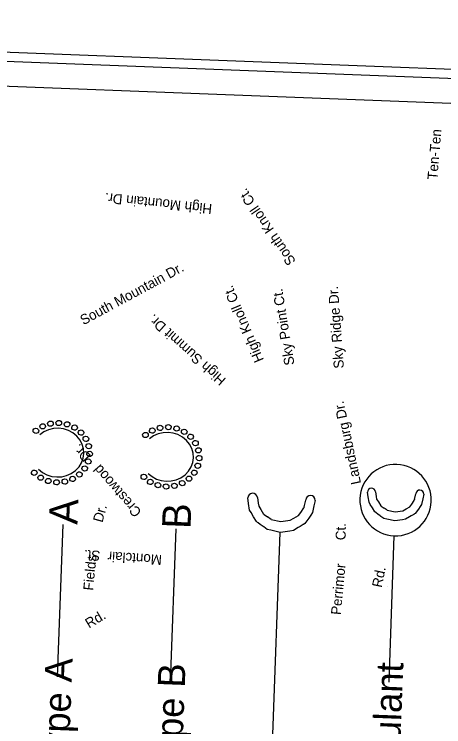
# Model space of a CAD drawing. Extents: x 1654773 to 2116434, y 680831 to 888488.
# Drawn here: x 2112569 to 2113644, y 699067 to 700848 of the extents above; entities that cross this region are included whole.
import ezdxf

# ---------------------------------------------------------------- set-up
doc = ezdxf.new("R2010")
doc.units = 0
for name, color, linetype in [('EC Title Sheet CELL', 7, 'Continuous'), ('Exist Road Non-System Type 51 Label', 7, 'Continuous'), ('Exist Road Secondary Type 51 Label', 7, 'Continuous'), ('Scratch_Level_6', 7, 'Continuous'), ('Sheet Plot Border Inside CELL', 7, 'Continuous'), ('Sheet Plot Border Outside CELL', 7, 'Continuous')]:
    doc.layers.add(name, color=color, linetype=linetype)

msp = doc.modelspace()

# ---------------------------------------------------------------- linework, layer by layer
at = {"layer": 'EC Title Sheet CELL'}
for p, q in [((2112677.5, 699192.2), (2112691.7, 699573.1)), ((2112960.3, 699178.9), (2112974.5, 699562.2)), ((2113199.7, 698582.8), (2113235, 699552.9)), ((2113507.1, 699178.4), (2113519.9, 699544.4))]:
    msp.add_line(p, q, dxfattribs=at)
for centre, major_axis in [((2112640.4, 699818), (-7.07, 0.27)), ((2112659.9, 699824.7), (-7.07, 0.27)), ((2112680.7, 699826.4), (-7.07, 0.27)), ((2112701.3, 699823.1), (-7.07, 0.27)), ((2112720.2, 699814.9), (-7.07, 0.27)), ((2112934.1, 699814.1), (-7.07, 0.27)), ((2112954.9, 699815.9), (-7.07, 0.27)), ((2112623.4, 699806.9), (-7.07, 0.27)), ((2112736.3, 699802.5), (-7.07, 0.27)), ((2112897.6, 699796.3), (-7.07, 0.27)), ((2112914.6, 699807.5), (-7.07, 0.27)), ((2112975.5, 699812.6), (-7.07, 0.27)), ((2112994.5, 699804.4), (-7.07, 0.27)), ((2112748.4, 699786.7), (7.07, -0.27)), ((2113010.5, 699792), (-7.07, 0.27)), ((2112755.7, 699768.5), (7.07, -0.27)), ((2113022.6, 699776.2), (7.07, -0.27)), ((2112757.7, 699749.2), (7.07, -0.27)), ((2113029.9, 699758), (7.07, -0.27)), ((2112754.3, 699730.2), (7.07, -0.27)), ((2113031.9, 699738.7), (7.07, -0.27)), ((2112745.6, 699712.6), (7.07, -0.27)), ((2113028.5, 699719.6), (7.07, -0.27)), ((2112619.3, 699702.1), (7.07, -0.27)), ((2112635.4, 699689.7), (7.07, -0.27)), ((2112732.3, 699697.8), (7.07, -0.27)), ((2112893.5, 699691.6), (7.07, -0.27)), ((2113019.8, 699702.1), (7.07, -0.27)), ((2112654.4, 699681.5), (7.07, -0.27)), ((2112675, 699678.2), (7.07, -0.27)), ((2112695.8, 699680), (7.07, -0.27)), ((2112715.3, 699686.6), (7.07, -0.27)), ((2112909.6, 699679.2), (7.07, -0.27)), ((2112989.5, 699676.1), (7.07, -0.27)), ((2113006.5, 699687.2), (7.07, -0.27)), ((2112928.6, 699671), (7.07, -0.27)), ((2112949.2, 699667.7), (7.07, -0.27)), ((2112970, 699669.4), (7.07, -0.27))]:
    msp.add_ellipse(centre, major_axis=major_axis, ratio=0.927398, dxfattribs=at)
for centre in [(2112677.8, 699752.3), (2112952, 699741.8)]:
    msp.add_ellipse(centre, major_axis=(-65.6, 2.5), ratio=0.927398, start_param=0.785389, end_param=5.497624, dxfattribs=at)
at = {"layer": 'Exist Road Non-System Type 51 Label'}
msp.add_line((2113502.3, 699418), (2113502.1, 699418), dxfattribs=at)
at = {"layer": 'Scratch_Level_6'}
for p, q in [((2113473.4, 699654.2), (2113475.1, 699642.4)), ((2113570.8, 699635.3), (2113574, 699649.2)), ((2113177.9, 699639.9), (2113179.8, 699625.8)), ((2113179.8, 699625.8), (2113180.9, 699618.6)), ((2113294.5, 699617.2), (2113298.4, 699633.9)), ((2113475.1, 699642.4), (2113476, 699636.4)), ((2113476, 699636.4), (2113480.3, 699629.1)), ((2113480.3, 699629.1), (2113486.1, 699619.6)), ((2113563.7, 699623.5), (2113570.2, 699632.8)), ((2113570.8, 699635.3), (2113570.2, 699632.8)), ((2113180.9, 699618.6), (2113186.1, 699609.9)), ((2113186.1, 699609.9), (2113193.1, 699598.5)), ((2113286, 699603.1), (2113293.8, 699614.2)), ((2113294.5, 699617.2), (2113293.8, 699614.2)), ((2113487.6, 699618.6), (2113486.1, 699619.6)), ((2113487.6, 699618.6), (2113494.7, 699613.8)), ((2113502.3, 699608.7), (2113494.7, 699613.8)), ((2113502.3, 699608.7), (2113522, 699604.4)), ((2113522.1, 699604.4), (2113541.5, 699606.9)), ((2113541.5, 699606.9), (2113549.5, 699611.5)), ((2113549.5, 699611.5), (2113559.2, 699617)), ((2113559.2, 699617), (2113563.7, 699623.5)), ((2113194.9, 699597.3), (2113193.1, 699598.5)), ((2113194.9, 699597.3), (2113203.3, 699591.5)), ((2113212.4, 699585.4), (2113203.3, 699591.5)), ((2113269, 699588.7), (2113280.6, 699595.3)), ((2113280.6, 699595.3), (2113286, 699603.1)), ((2113522.1, 699604.4), (2113522, 699604.4)), ((2113212.4, 699585.4), (2113236.1, 699580.2)), ((2113236.2, 699580.2), (2113236.1, 699580.2)), ((2113236.2, 699580.2), (2113259.4, 699583.3)), ((2113259.4, 699583.3), (2113269, 699588.7))]:
    msp.add_line(p, q, dxfattribs=at)
msp.add_lwpolyline([(2110171.4, 700758.7), (2109883.7, 693264.2), (2115129.9, 693062.9), (2115417.5, 700557.4)], close=True, dxfattribs=at)
for points in [[(2113593.9, 699648.4), (2113591.4, 699636.7), (2113588.5, 699623.1), (2113584.8, 699617.8), (2113580.4, 699611.4), (2113572.5, 699600.1), (2113572.3, 699599.9), (2113569.4, 699598.2), (2113568.9, 699597.9), (2113562.6, 699594.1), (2113558.2, 699591.5), (2113548.5, 699585.7), (2113540.6, 699584.5), (2113521.2, 699581.6), (2113521.2, 699581.6), (2113501.4, 699586.1), (2113493.7, 699587.9), (2113486.6, 699593), (2113485.2, 699594.1), (2113479.2, 699598.4), (2113474.6, 699601.6), (2113473.6, 699602.4), (2113471.3, 699604.1), (2113471.2, 699604.1), (2113465.3, 699614.1), (2113460.1, 699623), (2113456.9, 699628.3), (2113454.8, 699641.7), (2113453, 699653.4)], [(2113322.2, 699633), (2113319.2, 699619), (2113315.7, 699602.6), (2113311.3, 699596.3), (2113306, 699588.6), (2113296.6, 699575.1), (2113296.3, 699574.9), (2113292.8, 699572.8), (2113292.2, 699572.4), (2113284.7, 699567.9), (2113279.4, 699564.8), (2113267.8, 699557.8), (2113258.4, 699556.4), (2113235.1, 699552.9), (2113235, 699552.9), (2113211.4, 699558.4), (2113202.2, 699560.5), (2113193.7, 699566.6), (2113191.9, 699567.8), (2113184.7, 699573), (2113179.3, 699576.9), (2113178, 699577.9), (2113175.3, 699579.8), (2113175.2, 699579.9), (2113168.1, 699591.9), (2113161.8, 699602.5), (2113158.1, 699608.9), (2113155.6, 699624.9), (2113153.4, 699639)]]:
    msp.add_lwpolyline(points, dxfattribs=at)
for centre, radius, start, end in [((2113523.3, 699633.6), 89.3, 357.802, 177.802), ((2113463.3, 699653), 10.3, 6.6894, 177.802), ((2113165.7, 699638.5), 12.3, 6.6894, 177.802), ((2113310.3, 699633.5), 11.9, 357.802, 177.802), ((2113584, 699648.8), 9.97, 357.802, 177.802), ((2113523.3, 699633.6), 89.3, 177.802, 357.802)]:
    msp.add_arc(centre, radius, start, end, dxfattribs=at)
at = {"layer": 'Sheet Plot Border Inside CELL'}
msp.add_lwpolyline([(2115112.9, 692295.5), (2115432.4, 700619.3), (2110161.3, 700821.7), (2109841.8, 692497.8)], close=True, dxfattribs=at)
at = {"layer": 'Sheet Plot Border Outside CELL'}
msp.add_lwpolyline([(2115210.4, 692226.7), (2115533.2, 700638), (2110062.2, 700848), (2109739.4, 692436.7)], close=True, dxfattribs=at)

# ---------------------------------------------------------------- texts
at = {"layer": 'EC Title Sheet CELL'}
for s, height, p in [('A', 71.4, (2112727.3, 699571.7)), ('B', 71.4, (2113010.2, 699560.9)), ('Rock Pipe Inlet Sediment Trap Type A', 67.733, (2112656.2, 697698.5)), ('Rock Pipe Inlet Sediment Trap Type B', 67.733, (2112939, 697685.2)), ('Excelsior Wattle Check with Flocculant', 67.828, (2113483.2, 697670.5))]:
    msp.add_text(s, height=height, rotation=87.802, dxfattribs=at).set_placement(p)
at = {"layer": 'Exist Road Non-System Type 51 Label'}
for s, height, rotation, p in [('South Knoll Ct.', 25.049, 124.3076, (2113274.7, 700230.8)), ('High Mountain Dr.', 25.049, 173.9082, (2113065.3, 700373.2)), ('South Mountain Dr.', 25.049, 28.391, (2112742.5, 700070.4)), ('High Knoll Ct.', 25.049, 113.0327, (2113194.3, 699984.1)), ('Sky Point Ct.', 25.049, 99.1275, (2113270.5, 699972.5)), ('Sky Ridge Dr.', 25.049, 94.1517, (2113394.1, 699963.3)), ('High Summit Dr.', 25.049, 138.0337, (2113100.8, 699936.2)), ('Landsburg Dr.', 25.049, 102.0162, (2113437.2, 699675.6)), ('Ct.', 25.05, 89.5945, (2113398.5, 699533.3)), ('Montclair  St.', 25.049, 176.0981, (2112939.4, 699496.1)), ('Perrimor', 25.05, 84.6804, (2113386.4, 699345.9))]:
    msp.add_text(s, height=height, rotation=rotation, dxfattribs=at).set_placement(p)
at = {"layer": 'Exist Road Secondary Type 51 Label'}
for s, rotation, p in [('Ten-Ten', 85.3516, (2113627.8, 700433.7)), ('Dr.', 134.058, (2112762.6, 699744.4)), ('Crestwood', 131.094, (2112889.4, 699604.4)), ('Dr.', 74.5399, (2112789.8, 699576.2)), ('Fields', 84.3741, (2112766.6, 699406.8)), ('Rd.', 78.2076, (2113488.5, 699413.7)), ('Rd.', 31.0864, (2112756.3, 699312.3))]:
    msp.add_text(s, height=25.05, rotation=rotation, dxfattribs=at).set_placement(p)

doc.saveas('drawing.dxf')
